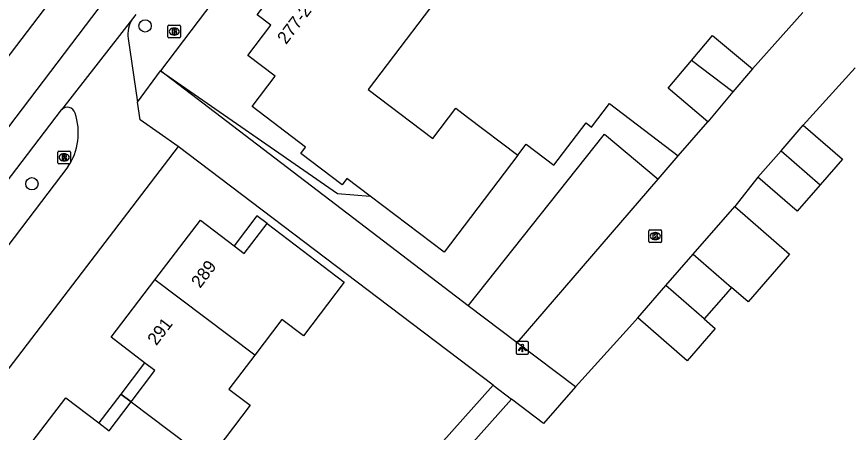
# Model space of a CAD drawing. Extents: x 158474 to 159560, y 388525 to 389605.
# Drawn here: x 158772.8 to 158838.9, y 388963.4 to 388996.4 of the extents above; entities that cross this region are included whole.
import ezdxf

# ---------------------------------------------------------------- set-up
doc = ezdxf.new("R2010")
doc.units = 0
for name, color, linetype in [('IMGEO_Boom', 7, 'Continuous'), ('IMGEO_Brandkraan', 7, 'Continuous'), ('IMGEO_Kolk', 7, 'Continuous'), ('IMGEO_Lichtpunt', 7, 'Continuous'), ('IMGEO_Pand', 7, 'Continuous'), ('IMGEO_Pand_nummerreeks', 7, 'Continuous'), ('IMGEO_Pand_overbouw', 7, 'Continuous'), ('IMGEO_Rijbaan_lokaal_gesloten', 7, 'Continuous'), ('IMGEO_Rijbaan_lokaal_open', 7, 'Continuous'), ('IMGEO_Rioolput', 7, 'Continuous'), ('IMGEO_Voetpad_open', 7, 'Continuous')]:
    doc.layers.add(name, color=color, linetype=linetype)

msp = doc.modelspace()

# ---------------------------------------------------------------- linework, layer by layer
at = {"layer": 'IMGEO_Boom'}
for centre in [(158783.02, 388995.655), (158774.051, 388983.139)]:
    msp.add_circle(centre, 0.489, dxfattribs=at)
at = {"layer": 'IMGEO_Brandkraan'}
for p, q in [((158784.827, 388994.782), (158784.827, 388995.634)), ((158784.902, 388995.708), (158785.754, 388995.708)), ((158785.315, 388995.488), (158785.34, 388995.488)), ((158785.828, 388995.634), (158785.828, 388994.782)), ((158785.338, 388994.928), (158785.313, 388994.928)), ((158785.754, 388994.708), (158784.902, 388994.708))]:
    msp.add_line(p, q, dxfattribs=at)
for points in [[(158784.827, 388994.782), (158784.827, 388995.634)], [(158784.902, 388995.708), (158785.754, 388995.708)], [(158785.175, 388995.408), (158785.175, 388995.008), (158785.388, 388995.008)], [(158785.406, 388995.408), (158785.175, 388995.408)], [(158785.828, 388995.634), (158785.828, 388994.782)], [(158785.354, 388995.327), (158785.3, 388995.327), (158785.3, 388995.251)], [(158785.3, 388995.251), (158785.353, 388995.251)], [(158785.362, 388995.175), (158785.3, 388995.175), (158785.3, 388995.094)], [(158785.3, 388995.094), (158785.362, 388995.094)], [(158785.754, 388994.708), (158784.902, 388994.708)]]:
    msp.add_lwpolyline(points, dxfattribs=at)
for centre, radius, start, end in [((158784.904, 388995.632), 0.0765, 91.55205, 178.44795), ((158784.904, 388995.632), 0.0765, 91.55205, 178.44795), ((158785.41, 388995.263), 0.145, 59.4692, 91.53667), ((158785.752, 388995.632), 0.0765, 1.55205, 88.44795), ((158785.752, 388995.632), 0.0765, 1.55205, 88.44795), ((158784.904, 388994.784), 0.0765, 181.55205, 268.44795), ((158784.904, 388994.784), 0.0765, 181.55205, 268.44795), ((158785.355, 388995.289), 0.0379, 267.82845, 90.93552), ((158785.363, 388995.134), 0.0404, 269.87594, 90.50774), ((158785.394, 388995.259), 0.251, 268.66757, 293.53466), ((158785.435, 388995.31), 0.0922, 285.51372, 58.15012), ((158785.44, 388995.118), 0.105, 301.31148, 78.98903), ((158785.752, 388994.784), 0.0765, 271.55205, 358.44795), ((158785.752, 388994.784), 0.0765, 271.55205, 358.44795)]:
    msp.add_arc(centre, radius, start, end, dxfattribs=at)
for centre, major_axis, ratio, start_param, end_param in [((158785.314, 388995.208), (-0.387, 0.002), 0.722429, 4.712389, 7.853982), ((158785.339, 388995.208), (-0.39, 0.002), 0.717154, 1.570796, 4.712389)]:
    msp.add_ellipse(centre, major_axis=major_axis, ratio=ratio, start_param=start_param, end_param=end_param, dxfattribs=at)
at = {"layer": 'IMGEO_Kolk'}
for p, q in [((158822.957, 388978.562), (158822.957, 388979.414)), ((158823.032, 388979.488), (158823.884, 388979.488)), ((158823.445, 388979.268), (158823.47, 388979.268)), ((158823.958, 388979.414), (158823.958, 388978.562)), ((158823.884, 388978.488), (158823.032, 388978.488)), ((158823.468, 388978.708), (158823.443, 388978.708))]:
    msp.add_line(p, q, dxfattribs=at)
for points in [[(158822.957, 388978.562), (158822.957, 388979.414)], [(158823.032, 388979.488), (158823.884, 388979.488)], [(158823.278, 388979.188), (158823.401, 388979.188), (158823.401, 388979.037), (158823.531, 388979.188), (158823.695, 388979.188), (158823.549, 388979.037), (158823.702, 388978.788), (158823.55, 388978.788), (158823.465, 388978.952), (158823.401, 388978.885), (158823.401, 388978.788), (158823.278, 388978.788), (158823.278, 388979.188)], [(158823.958, 388979.414), (158823.958, 388978.562)], [(158823.884, 388978.488), (158823.032, 388978.488)]]:
    msp.add_lwpolyline(points, dxfattribs=at)
for centre, start, end in [((158823.034, 388979.412), 91.55205, 178.44795), ((158823.034, 388979.412), 91.55205, 178.44795), ((158823.882, 388979.412), 1.55205, 88.44795), ((158823.882, 388979.412), 1.55205, 88.44795), ((158823.034, 388978.564), 181.55205, 268.44795), ((158823.034, 388978.564), 181.55205, 268.44795), ((158823.882, 388978.564), 271.55205, 358.44795), ((158823.882, 388978.564), 271.55205, 358.44795)]:
    msp.add_arc(centre, 0.0765, start, end, dxfattribs=at)
for centre, major_axis, ratio, start_param, end_param in [((158823.444, 388978.988), (-0.387, 0.002), 0.722429, 4.712389, 7.853982), ((158823.469, 388978.988), (-0.39, 0.002), 0.717154, 1.570796, 4.712389)]:
    msp.add_ellipse(centre, major_axis=major_axis, ratio=ratio, start_param=start_param, end_param=end_param, dxfattribs=at)
at = {"layer": 'IMGEO_Lichtpunt'}
for p, q in [((158812.421, 388970.524), (158812.421, 388969.717)), ((158812.421, 388970.524), (158812.421, 388969.717)), ((158813.323, 388970.619), (158812.515, 388970.619)), ((158813.323, 388970.619), (158812.515, 388970.619)), ((158813.417, 388969.717), (158813.417, 388970.524)), ((158813.417, 388969.717), (158813.417, 388970.524)), ((158812.515, 388969.623), (158813.323, 388969.623)), ((158812.515, 388969.623), (158813.323, 388969.623))]:
    msp.add_line(p, q, dxfattribs=at)
for points in [[(158812.795, 388970.188), (158812.834, 388970.16), (158812.646, 388969.898), (158812.608, 388969.925), (158812.795, 388970.188)], [(158812.897, 388970.14), (158812.944, 388970.14), (158812.944, 388969.818), (158812.897, 388969.818), (158812.897, 388970.14)], [(158813.007, 388970.16), (158813.045, 388970.187), (158813.232, 388969.925), (158813.193, 388969.897), (158813.007, 388970.16)]]:
    msp.add_lwpolyline(points, dxfattribs=at)
msp.add_circle((158812.92, 388970.322), 0.0994, dxfattribs=at)
for centre, start, end in [((158812.515, 388970.524), 90, 180), ((158812.515, 388970.524), 90, 180), ((158813.323, 388970.524), 0, 90), ((158813.323, 388970.524), 0, 90), ((158812.515, 388969.717), 180, 270), ((158812.515, 388969.717), 180, 270), ((158813.323, 388969.717), 270, 0), ((158813.323, 388969.717), 270, 360)]:
    msp.add_arc(centre, 0.0946, start, end, dxfattribs=at)
at = {"layer": 'IMGEO_Pand'}
for points in [[(158800.849, 388982.165), (158799.013, 388983.56), (158798.633, 388983.06), (158795.36, 388985.546), (158795.743, 388986.051), (158791.502, 388989.272), (158793.321, 388991.666), (158791.158, 388993.308), (158792.98, 388995.707), (158791.896, 388996.53), (158794.533, 389000), (158795.847, 389001.731), (158796.94, 389000.901), (158798.089, 389002.414), (158797.609, 389002.778), (158799.842, 389005.718)], [(158807.652, 388999.783), (158800.693, 388990.621), (158805.828, 388986.721), (158807.658, 388989.13), (158808.582, 388988.428), (158812.564, 388985.404)], [(158826.324, 388992.922), (158828.001, 388994.91), (158831.154, 388992.251)], [(158827.616, 388988.058), (158824.464, 388990.717), (158826.324, 388992.922)], [(158829.613, 388990.424), (158826.324, 388992.922)], [(158831.154, 388992.251), (158829.613, 388990.424)], [(158829.613, 388990.424), (158827.616, 388988.058)], [(158833.428, 388985.763), (158835.186, 388987.785)], [(158835.186, 388987.785), (158838.287, 388985.089), (158836.521, 388983.058)], [(158831.595, 388983.655), (158833.428, 388985.763)], [(158833.428, 388985.763), (158836.521, 388983.058)], [(158812.564, 388985.404), (158806.718, 388977.708), (158800.849, 388982.165)], [(158836.521, 388983.058), (158834.696, 388980.959), (158831.595, 388983.655)], [(158826.456, 388977.555), (158829.755, 388981.347)], [(158829.755, 388981.347), (158834.105, 388977.563), (158830.806, 388973.77), (158829.5, 388974.907)], [(158783.799, 388975.518), (158787.405, 388980.254), (158790.075, 388978.221), (158790.877, 388977.611), (158792.683, 388979.982), (158798.797, 388975.327), (158795.561, 388971.077), (158793.858, 388972.374), (158791.703, 388969.543)], [(158824.288, 388975.063), (158826.456, 388977.555)], [(158826.456, 388977.555), (158829.5, 388974.907)], [(158781.913, 388965.838), (158783.801, 388968.317), (158782.978, 388968.944), (158780.329, 388970.961), (158783.799, 388975.518)], [(158791.703, 388969.543), (158783.799, 388975.518)], [(158822.07, 388972.513), (158824.288, 388975.063)], [(158827.332, 388972.415), (158824.288, 388975.063)], [(158829.5, 388974.907), (158829.044, 388974.383), (158827.332, 388972.415)], [(158827.332, 388972.415), (158828.209, 388971.652), (158825.991, 388969.102), (158822.07, 388972.513)], [(158791.703, 388969.543), (158789.659, 388966.858), (158791.351, 388965.57), (158788.034, 388961.214)], [(158773.114, 388961.419), (158776.723, 388966.159), (158779.341, 388964.166), (158780.164, 388963.54), (158781.913, 388965.838)], [(158781.913, 388965.838), (158788.034, 388961.214)]]:
    msp.add_lwpolyline(points, dxfattribs=at)
at = {"layer": 'IMGEO_Pand_overbouw'}
for points in [[(158791.88, 388980.593), (158790.075, 388978.221), (158790.877, 388977.611), (158792.683, 388979.982)], [(158781.088, 388966.461), (158781.913, 388965.838), (158783.801, 388968.317), (158782.978, 388968.944)], [(158781.913, 388965.838), (158781.088, 388966.461), (158779.341, 388964.166), (158780.164, 388963.54)]]:
    msp.add_lwpolyline(points, close=True, dxfattribs=at)
at = {"layer": 'IMGEO_Rijbaan_lokaal_gesloten'}
for points in [[(158654.546, 388838.744), (158652.694, 388840.633), (158668.364, 388856.424), (158683.318, 388872.712), (158697.002, 388889.186), (158717.328, 388915.448), (158737.178, 388941.567), (158754.114, 388963.852), (158766.121, 388979.65), (158778.301, 388995.677), (158798.192, 389021.851), (158809.433, 389036.528), (158811.777, 389039.288), (158814.069, 389041.449), (158818.297, 389044.22), (158821.97, 389045.718)], [(158779.752, 389003.234), (158771.022, 388991.766)], [(158782.009, 388996.219), (158776.401, 388989.012)], [(158782.277, 388996.564), (158782.009, 388996.219)], [(158725.749, 388922.405), (158730.616, 388928.858), (158776.401, 388989.012)]]:
    msp.add_lwpolyline(points, dxfattribs=at)
at = {"layer": 'IMGEO_Rijbaan_lokaal_open'}
for points in [[(158831.154, 388992.251), (158835.151, 388996.719)], [(158781.677, 388994.66), (158782.422, 388989.622)], [(158839.303, 388992.327), (158835.186, 388987.785)], [(158785.644, 388986.089), (158782.63, 388988.213), (158782.422, 388989.622)], [(158825.277, 388985.344), (158827.616, 388988.058)], [(158785.644, 388986.089), (158736.904, 388922.269)], [(158823.69, 388983.501), (158825.277, 388985.344)], [(158776.899, 388984.473), (158772.125, 388978.207)], [(158812.511, 388970.525), (158823.69, 388983.501)], [(158831.595, 388983.655), (158829.755, 388981.347)], [(158822.07, 388972.513), (158821.643, 388972.038), (158817.123, 388967.026)], [(158817.123, 388967.026), (158812.511, 388970.525)]]:
    msp.add_lwpolyline(points, dxfattribs=at)
for centre, radius, start, end in [((158783.911, 388994.999), 2.259, 147.32201, 188.63409), ((158776.858, 388988.573), 0.633, 16.13497, 136.1219), ((158772.856, 388987.185), 4.868, 326.14793, 18.7453)]:
    msp.add_arc(centre, radius, start, end, dxfattribs=at)
at = {"layer": 'IMGEO_Rioolput'}
for p, q in [((158776.102, 388984.804), (158776.102, 388985.656)), ((158776.177, 388985.73), (158777.029, 388985.73)), ((158776.59, 388985.51), (158776.615, 388985.51)), ((158777.103, 388985.656), (158777.103, 388984.804)), ((158776.613, 388984.95), (158776.588, 388984.95)), ((158777.029, 388984.73), (158776.177, 388984.73))]:
    msp.add_line(p, q, dxfattribs=at)
for points in [[(158776.102, 388984.804), (158776.102, 388985.656)], [(158776.177, 388985.73), (158777.029, 388985.73)], [(158777.103, 388985.656), (158777.103, 388984.804)], [(158776.691, 388985.428), (158776.439, 388985.43), (158776.439, 388985.03)], [(158776.439, 388985.03), (158776.563, 388985.03), (158776.563, 388985.192), (158776.574, 388985.192)], [(158776.617, 388985.349), (158776.563, 388985.349), (158776.563, 388985.268)], [(158776.563, 388985.268), (158776.615, 388985.268)], [(158776.621, 388985.163), (158776.692, 388985.03), (158776.832, 388985.03), (158776.767, 388985.156)], [(158777.029, 388984.73), (158776.177, 388984.73)]]:
    msp.add_lwpolyline(points, dxfattribs=at)
for centre, radius, start, end in [((158776.179, 388985.654), 0.0765, 91.55205, 178.44795), ((158776.179, 388985.654), 0.0765, 91.55205, 178.44795), ((158777.027, 388985.654), 0.0765, 1.55205, 88.44795), ((158777.027, 388985.654), 0.0765, 1.55205, 88.44795), ((158776.573, 388985.139), 0.0533, 26.02933, 88.69889), ((158776.599, 388985.457), 0.19, 274.7715, 282.96867), ((158776.623, 388985.253), 0.0964, 77.00612, 93.18647), ((158776.637, 388985.31), 0.0378, 276.66336, 79.67722), ((158776.69, 388985.318), 0.109, 350.36119, 89.41601), ((158776.688, 388985.318), 0.112, 277.58423, 350.98172), ((158776.672, 388985.103), 0.108, 29.51342, 73.79051), ((158776.179, 388984.806), 0.0765, 181.55205, 268.44795), ((158776.179, 388984.806), 0.0765, 181.55205, 268.44795), ((158777.027, 388984.806), 0.0765, 271.55205, 358.44795), ((158777.027, 388984.806), 0.0765, 271.55205, 358.44795)]:
    msp.add_arc(centre, radius, start, end, dxfattribs=at)
for centre, major_axis, ratio, start_param, end_param in [((158776.589, 388985.23), (-0.387, 0.002), 0.722429, 4.712389, 7.853982), ((158776.614, 388985.23), (-0.39, 0.002), 0.717154, 1.570796, 4.712389)]:
    msp.add_ellipse(centre, major_axis=major_axis, ratio=ratio, start_param=start_param, end_param=end_param, dxfattribs=at)
at = {"layer": 'IMGEO_Voetpad_open'}
for points in [[(158880.543, 389059.085), (158818.621, 389037.472), (158790.211, 389000), (158784.237, 388992.09)], [(158782.422, 388989.622), (158784.237, 388992.09)], [(158784.237, 388992.09), (158798.278, 388982.376), (158800.849, 388982.165)], [(158808.636, 388973.466), (158784.237, 388992.09)], [(158812.564, 388985.404), (158813.219, 388986.28), (158815.415, 388984.601), (158817.981, 388987.959), (158818.409, 388987.636), (158819.836, 388989.503), (158825.277, 388985.344)], [(158808.636, 388973.466), (158819.428, 388987.085), (158823.69, 388983.501)], [(158810.599, 388967.168), (158801.457, 388974.099), (158785.644, 388986.089)], [(158812.511, 388970.525), (158808.636, 388973.466)], [(158812.051, 388966.068), (158799.647, 388952.134), (158787.864, 388938.897), (158785.78, 388937.796), (158785.709, 388939.207), (158786.508, 388940.104), (158795.974, 388950.739), (158810.599, 388967.168)], [(158810.599, 388967.168), (158812.051, 388966.068)], [(158817.123, 388967.026), (158814.596, 388964.138), (158812.051, 388966.068)]]:
    msp.add_lwpolyline(points, dxfattribs=at)

# ---------------------------------------------------------------- texts
at = {"layer": 'IMGEO_Pand_nummerreeks'}
for s, rotation, p in [('277-287', 52.77514, (158794.198, 388994.137)), ('289', 52.71212, (158787.376, 388974.802)), ('291', 52.71212, (158783.907, 388970.246))]:
    msp.add_text(s, height=1, rotation=rotation, dxfattribs=at).set_placement(p)

doc.saveas('drawing.dxf')
